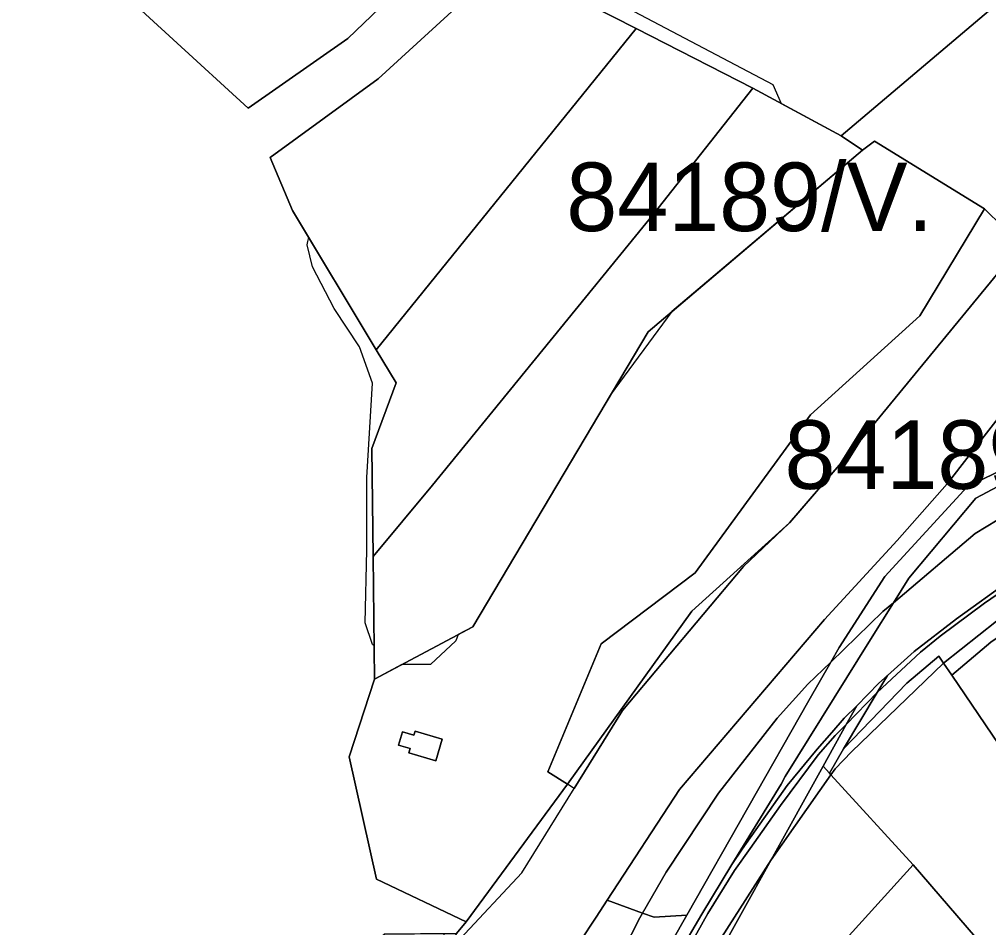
# Model space of a CAD drawing. Extents: x -477304 to -465429, y -1159113 to -1149210.
# Drawn here: x -475692.5 to -475480.3, y -1154385.5 to -1154186.7 of the extents above; entities that cross this region are included whole.
import ezdxf

# ---------------------------------------------------------------- set-up
doc = ezdxf.new("R2010")
doc.units = 0
for name, color, linetype in [('BPEJ_s', 7, 'Continuous'), ('orna_s', 7, 'Continuous'), ('ostatni_s', 7, 'Continuous'), ('PUPFL_s', 7, 'Continuous'), ('trav_porost_s', 7, 'Continuous'), ('voda_s', 7, 'Continuous')]:
    doc.layers.add(name, color=color, linetype=linetype)

msp = doc.modelspace()

# ---------------------------------------------------------------- linework, layer by layer
at = {"layer": 'BPEJ_s'}
for points in [[(-475567.62, -1154179.77), (-475527.61, -1154200.97), (-475525.77, -1154205.09), (-475512.65, -1154212.2), (-475507.98, -1154215.32), (-475549.67, -1154250.64), (-475563.18, -1154268.99), (-475593.29, -1154319.68), (-475596.43, -1154321.35), (-475596.98, -1154322.75), (-475602.54, -1154327.92), (-475608.78, -1154327.92), (-475614.77, -1154331.11), (-475614.86, -1154323.82), (-475615.25, -1154323.55), (-475616.84, -1154318.78), (-475616.44, -1154302.88), (-475616.44, -1154286.97), (-475615.25, -1154266.3), (-475618.03, -1154258.35), (-475623.59, -1154250), (-475628.36, -1154240.86), (-475629.55, -1154236.08), (-475629.37, -1154235.29), (-475629.18, -1154234.44), (-475632.72, -1154228.55), (-475637.63, -1154216.91), (-475613.99, -1154199.7), (-475585.15, -1154173.3)], [(-475613.99, -1154199.7), (-475585.15, -1154173.3)], [(-475567.62, -1154179.77), (-475527.61, -1154200.97), (-475525.77, -1154205.09), (-475512.65, -1154212.2), (-475507.98, -1154215.32), (-475549.67, -1154250.64), (-475563.18, -1154268.99), (-475593.29, -1154319.68), (-475596.43, -1154321.35), (-475596.98, -1154322.75), (-475602.54, -1154327.92), (-475608.78, -1154327.92), (-475614.77, -1154331.11), (-475614.86, -1154323.82), (-475615.25, -1154323.55), (-475616.84, -1154318.78), (-475616.44, -1154302.88), (-475616.44, -1154286.97), (-475615.25, -1154266.3), (-475618.03, -1154258.35), (-475623.59, -1154250), (-475628.36, -1154240.86), (-475629.55, -1154236.08), (-475629.37, -1154235.29), (-475629.18, -1154234.44), (-475632.72, -1154228.55), (-475637.63, -1154216.91), (-475613.99, -1154199.7)], [(-475731, -1154455.5), (-475685.5, -1154443.5), (-475658.17, -1154422.75), (-475639.93, -1154406.49), (-475634.73, -1154404.95), (-475631.5, -1154402.5), (-475628.5, -1154401.5), (-475623.92, -1154398.28), (-475621.39, -1154394.73), (-475612.62, -1154386.98), (-475599.44, -1154386.85), (-475596.82, -1154386.82), (-475597.49, -1154388.37), (-475596, -1154388), (-475582.5, -1154373.5), (-475571.09, -1154355.09), (-475572.52, -1154354.12), (-475576.83, -1154351.41), (-475565.18, -1154323.39), (-475544.55, -1154307.85), (-475519.37, -1154273.24), (-475495.41, -1154251.56), (-475481.23, -1154228.2), (-475473.22, -1154236.05)], [(-475639, -1154586), (-475632, -1154559), (-475633.5, -1154543.56), (-475637, -1154507.5), (-475628.67, -1154485.64), (-475625, -1154476), (-475604.41, -1154404.33), (-475600, -1154389), (-475599.44, -1154386.85), (-475596.82, -1154386.82), (-475597.49, -1154388.37), (-475596, -1154388), (-475582.5, -1154373.5), (-475571.09, -1154355.09), (-475560.5, -1154338), (-475534, -1154306.5), (-475524, -1154296.97), (-475523.89, -1154296.86), (-475508.55, -1154279.03), (-475473.22, -1154236.05)]]:
    msp.add_lwpolyline(points, dxfattribs=at)
msp.add_lwpolyline([(-475473.22, -1154236.05), (-475508.55, -1154279.03), (-475523.89, -1154296.86), (-475524, -1154296.97), (-475534, -1154306.5), (-475560.5, -1154338), (-475571.09, -1154355.09), (-475572.52, -1154354.12), (-475576.83, -1154351.41), (-475565.18, -1154323.39), (-475544.55, -1154307.85), (-475519.37, -1154273.24), (-475495.41, -1154251.56), (-475481.23, -1154228.2)], close=True, dxfattribs=at)
at = {"layer": 'orna_s'}
for points in [[(-475481.26, -1154314.53), (-475490.92, -1154321.74), (-475495.28, -1154325.21), (-475504.75, -1154334.08), (-475502.52, -1154330.36), (-475496.65, -1154325.11), (-475487.4, -1154317.93), (-475475.62, -1154309.48), (-475465.15, -1154302.44), (-475455.29, -1154297.28), (-475447.05, -1154293.35), (-475435.79, -1154288.45), (-475427, -1154285.31), (-475409.33, -1154280.37), (-475398.38, -1154278.13), (-475391.57, -1154277.2), (-475391.61, -1154277.99), (-475404.7, -1154280.5), (-475422.23, -1154285.02), (-475437.56, -1154290.12), (-475454.36, -1154297.46), (-475469.21, -1154306.24)], [(-475475.44, -1154320.07), (-475479.85, -1154323.07), (-475488.4, -1154330.28), (-475490.2, -1154327.62), (-475478.6, -1154318.44), (-475452.58, -1154302.04), (-475435.8, -1154294.77), (-475420.54, -1154289.58), (-475403.9, -1154285.81), (-475391.89, -1154283.24), (-475392.05, -1154286.27), (-475410.21, -1154289.79), (-475428.95, -1154295.45), (-475447.26, -1154303.12), (-475463.43, -1154311.9), (-475472.14, -1154317.82)], [(-475434.02, -1154410.43), (-475488.4, -1154330.28), (-475479.85, -1154323.07), (-475475.44, -1154320.07), (-475427.04, -1154391.42), (-475429.04, -1154396.87)], [(-475490.2, -1154327.62), (-475488.4, -1154330.28), (-475434.02, -1154410.43), (-475457.14, -1154424.42), (-475483.2, -1154387.59), (-475496.89, -1154371.78), (-475514.86, -1154352.08), (-475513.91, -1154350.74), (-475510.38, -1154347.08)]]:
    msp.add_lwpolyline(points, close=True, dxfattribs=at)
at = {"layer": 'ostatni_s'}
for points in [[(-475429, -1154162.83), (-475467.72, -1154186.86), (-475478.48, -1154183.29), (-475512.65, -1154212.2), (-475531.93, -1154201.75), (-475557.51, -1154188.7), (-475583.1, -1154175.64)], [(-475471.25, -1154291.93), (-475483.28, -1154299.25), (-475501.18, -1154314.4), (-475497.82, -1154309.02), (-475483.18, -1154291.52), (-475457.82, -1154278.11)], [(-475475.62, -1154309.48), (-475487.4, -1154317.93), (-475496.65, -1154325.11), (-475502.52, -1154330.36), (-475504.39, -1154332.04), (-475509.23, -1154336.94), (-475511.94, -1154339.68), (-475514.7, -1154342.82), (-475517.85, -1154346.45), (-475524.44, -1154354.43), (-475534.28, -1154368.33), (-475536.55, -1154371.7), (-475525.78, -1154354.09), (-475524.91, -1154352.42), (-475506.21, -1154322.47), (-475501.18, -1154314.4), (-475483.28, -1154299.25), (-475471.25, -1154291.93)], [(-475547.98, -1154390.91), (-475543.16, -1154382.57), (-475536.55, -1154371.7), (-475534.28, -1154368.33), (-475524.44, -1154354.43), (-475517.85, -1154346.45), (-475514.7, -1154342.82), (-475511.94, -1154339.68), (-475509.23, -1154336.94), (-475511.53, -1154341.08), (-475513.94, -1154343.5), (-475517.64, -1154347.73), (-475525.93, -1154358.83), (-475532.55, -1154368.21), (-475535.95, -1154373.01), (-475541.83, -1154382.44), (-475549.8, -1154396.65)], [(-475549.8, -1154396.65), (-475541.83, -1154382.44), (-475535.95, -1154373.01), (-475532.55, -1154368.21), (-475525.93, -1154358.83), (-475517.64, -1154347.73), (-475513.94, -1154343.5), (-475511.53, -1154341.08), (-475516.6, -1154350.21), (-475527.96, -1154370.68), (-475538.83, -1154387.7)]]:
    msp.add_lwpolyline(points, dxfattribs=at)
for points in [[(-475468.98, -1154276.86), (-475449, -1154270.5), (-475447.33, -1154269.96), (-475451.89, -1154256.11), (-475447.22, -1154254.31), (-475447, -1154254.98), (-475448.33, -1154255.41), (-475447.49, -1154258.01), (-475446.15, -1154257.58), (-475443.98, -1154264.35), (-475430.63, -1154260.01), (-475434.1, -1154249.27), (-475402.53, -1154237.13), (-475390.95, -1154258.02), (-475405, -1154260.27), (-475423.09, -1154264.6), (-475458.7, -1154276.34), (-475484.98, -1154288.97), (-475489.4, -1154288.4), (-475469.65, -1154262.94), (-475463.12, -1154260.43), (-475470.7, -1154270.78)], [(-475514.92, -1154327.4), (-475513.1, -1154324.2), (-475503.04, -1154308.64), (-475484.98, -1154288.97), (-475458.7, -1154276.34), (-475423.09, -1154264.6), (-475405, -1154260.27), (-475422.7, -1154265.96), (-475457.82, -1154278.11), (-475483.18, -1154291.52), (-475497.82, -1154309.02), (-475501.18, -1154314.4), (-475503.47, -1154316.34)], [(-475481.26, -1154314.53), (-475469.21, -1154306.24), (-475454.36, -1154297.46), (-475437.56, -1154290.12), (-475422.23, -1154285.02), (-475404.7, -1154280.5), (-475391.61, -1154277.99), (-475391.78, -1154281.13), (-475391.89, -1154283.24), (-475403.9, -1154285.81), (-475420.54, -1154289.58), (-475435.8, -1154294.77), (-475452.58, -1154302.04), (-475478.6, -1154318.44), (-475490.2, -1154327.62), (-475491.22, -1154326.12), (-475498.22, -1154332.03), (-475512.15, -1154346.39), (-475504.75, -1154334.08), (-475495.28, -1154325.21), (-475490.92, -1154321.74)], [(-475560.13, -1154406.85), (-475546.44, -1154382.79), (-475519.7, -1154335.8), (-475514.92, -1154327.4), (-475503.47, -1154316.34), (-475501.18, -1154314.4), (-475506.21, -1154322.47), (-475524.91, -1154352.42), (-475525.78, -1154354.09), (-475536.55, -1154371.7), (-475543.16, -1154382.57), (-475547.98, -1154390.91), (-475568.51, -1154422.5)], [(-475546.44, -1154382.79), (-475553.59, -1154383.27), (-475556.1, -1154382.36), (-475550.91, -1154373.36), (-475539.48, -1154356.13), (-475526.66, -1154339.71), (-475519.94, -1154332.25), (-475514.92, -1154327.4), (-475519.7, -1154335.8)], [(-475512.15, -1154346.39), (-475498.22, -1154332.03), (-475491.22, -1154326.12), (-475490.2, -1154327.62), (-475510.38, -1154347.08), (-475513.91, -1154350.74), (-475514.86, -1154352.08), (-475515.21, -1154351.7)], [(-475509.23, -1154336.94), (-475504.39, -1154332.04), (-475502.52, -1154330.36), (-475504.75, -1154334.08), (-475511.53, -1154341.08)], [(-475511.53, -1154341.08), (-475504.75, -1154334.08), (-475512.15, -1154346.39), (-475515.21, -1154351.7), (-475516.6, -1154350.21)], [(-475599.97, -1154344.29), (-475601.38, -1154349.02), (-475607.28, -1154347.26), (-475607, -1154346.32), (-475609.51, -1154345.57), (-475608.65, -1154342.67), (-475606.14, -1154343.42), (-475605.87, -1154342.53)], [(-475527.96, -1154370.68), (-475516.6, -1154350.21), (-475515.21, -1154351.7), (-475514.86, -1154352.08)], [(-475538.83, -1154387.7), (-475527.96, -1154370.68), (-475541.24, -1154394.59)], [(-475546.44, -1154382.79), (-475560.13, -1154406.85), (-475568.51, -1154422.5), (-475579.97, -1154449.97), (-475583.73, -1154445.03), (-475574.25, -1154419.9), (-475565.96, -1154401.53), (-475556.68, -1154383.37), (-475556.1, -1154382.36), (-475553.59, -1154383.27)]]:
    msp.add_lwpolyline(points, close=True, dxfattribs=at)
at = {"layer": 'PUPFL_s'}
for points in [[(-475352.75, -1153984.87), (-475338.69, -1154011.34), (-475352.09, -1154014.95), (-475381.35, -1154022.83), (-475443.17, -1154025.66), (-475499.82, -1154029.51), (-475556.44, -1154021.02), (-475635.42, -1154012.08), (-475649.02, -1154046.75), (-475671.45, -1154068.19), (-475660.13, -1154079.7), (-475654.25, -1154085.13), (-475651.23, -1154087.99), (-475623.48, -1154114.25), (-475601.71, -1154149.02), (-475588.2, -1154168.75), (-475594.61, -1154165.94), (-475620.6, -1154190.85), (-475642.43, -1154206.13), (-475806.71, -1154055.75), (-475825.65, -1154044.41), (-475814.03, -1153985.87)], [(-475814.03, -1153985.87), (-475825.65, -1154044.41), (-475806.71, -1154055.75), (-475642.43, -1154206.13), (-475620.6, -1154190.85), (-475594.61, -1154165.94), (-475588.2, -1154168.75), (-475585.15, -1154173.3), (-475613.99, -1154199.7), (-475637.63, -1154216.91), (-475632.72, -1154228.55), (-475614.41, -1154259.01), (-475610.06, -1154266.26), (-475615.38, -1154280.61)], [(-475615.38, -1154280.61), (-475615.09, -1154304.29), (-475614.77, -1154331.11), (-475620.34, -1154348.16)], [(-475620.34, -1154348.16), (-475614.32, -1154374.89), (-475594.73, -1154384.24), (-475596.82, -1154386.82), (-475612.62, -1154386.98), (-475621.39, -1154394.73), (-475627.06, -1154402.68), (-475639.93, -1154406.49), (-475666.83, -1154430.47), (-475692.56, -1154448.71)]]:
    msp.add_lwpolyline(points, dxfattribs=at)
for points in [[(-475473.22, -1154236.05), (-475481.23, -1154228.2), (-475505.35, -1154213.34), (-475507.98, -1154215.32), (-475512.65, -1154212.2), (-475478.48, -1154183.29), (-475467.72, -1154186.86), (-475429, -1154162.83), (-475426.04, -1154160.45), (-475422.46, -1154165.86), (-475426.6, -1154166.59), (-475414.25, -1154197.63), (-475438.58, -1154204.34), (-475454.72, -1154212.8), (-475465.22, -1154223.55)], [(-475565.18, -1154323.39), (-475576.83, -1154351.41), (-475572.52, -1154354.12), (-475594.73, -1154384.24), (-475614.32, -1154374.89), (-475620.34, -1154348.16), (-475614.77, -1154331.11), (-475593.29, -1154319.68), (-475554.91, -1154255.08), (-475507.98, -1154215.32), (-475505.35, -1154213.34), (-475481.23, -1154228.2), (-475495.41, -1154251.56), (-475519.37, -1154273.24), (-475544.55, -1154307.85)], [(-475607.28, -1154347.26), (-475601.38, -1154349.02), (-475599.97, -1154344.29), (-475605.87, -1154342.53), (-475606.14, -1154343.42), (-475608.65, -1154342.67), (-475609.51, -1154345.57), (-475607, -1154346.32)]]:
    msp.add_lwpolyline(points, close=True, dxfattribs=at)
at = {"layer": 'trav_porost_s'}
for points in [[(-475637.63, -1154216.91), (-475613.99, -1154199.7), (-475585.15, -1154173.3), (-475583.1, -1154175.64), (-475557.51, -1154188.7), (-475614.41, -1154259.01), (-475632.72, -1154228.55)], [(-475531.93, -1154201.75), (-475553.75, -1154229.42), (-475602.05, -1154288.69), (-475615.09, -1154304.29), (-475615.38, -1154280.61), (-475610.06, -1154266.26), (-475614.41, -1154259.01), (-475557.51, -1154188.7)], [(-475615.09, -1154304.29), (-475602.05, -1154288.69), (-475553.75, -1154229.42), (-475531.93, -1154201.75), (-475512.65, -1154212.2), (-475507.98, -1154215.32), (-475554.91, -1154255.08), (-475593.29, -1154319.68), (-475614.77, -1154331.11)], [(-475473.22, -1154236.05), (-475508.55, -1154279.03), (-475523.9, -1154296.88), (-475545.3, -1154316.22), (-475572.52, -1154354.12), (-475576.83, -1154351.41), (-475565.18, -1154323.39), (-475544.55, -1154307.85), (-475519.37, -1154273.24), (-475495.41, -1154251.56), (-475481.23, -1154228.2)], [(-475550.91, -1154373.36), (-475556.1, -1154382.36), (-475563.87, -1154379.55), (-475548.04, -1154355.26), (-475516.26, -1154318.07), (-475500.36, -1154300.77), (-475489.4, -1154288.4), (-475484.98, -1154288.97), (-475503.04, -1154308.64), (-475513.1, -1154324.2), (-475514.92, -1154327.4), (-475519.94, -1154332.25), (-475526.66, -1154339.71), (-475539.48, -1154356.13)], [(-475541.24, -1154394.59), (-475527.96, -1154370.68), (-475514.86, -1154352.08), (-475496.89, -1154371.78), (-475528.32, -1154406.52)], [(-475509.34, -1154455.82), (-475528.72, -1154440.81), (-475536.42, -1154435.75), (-475541.79, -1154431.04), (-475534.27, -1154422.32), (-475537.4, -1154418.92), (-475538.34, -1154419.92), (-475539.47, -1154418.94), (-475538.56, -1154417.92), (-475537.44, -1154416.66), (-475534.42, -1154413.26), (-475528.32, -1154406.52), (-475496.89, -1154371.78), (-475483.2, -1154387.59), (-475457.14, -1154424.42), (-475492.65, -1154458.11)], [(-475565.96, -1154401.53), (-475574.25, -1154419.9), (-475583.73, -1154445.03), (-475591.13, -1154435.31), (-475587.85, -1154420.49), (-475580.57, -1154404.81), (-475566.27, -1154383.22), (-475563.87, -1154379.55), (-475556.1, -1154382.36), (-475556.68, -1154383.37)]]:
    msp.add_lwpolyline(points, close=True, dxfattribs=at)
at = {"layer": 'voda_s'}
for points in [[(-475638.79, -1154574.99), (-475635.34, -1154556), (-475629.49, -1154516.48), (-475628.16, -1154466.27), (-475624.86, -1154446.16), (-475614, -1154423.69), (-475611.22, -1154417.76), (-475607.97, -1154412.56), (-475596.82, -1154386.82), (-475594.73, -1154384.24), (-475572.52, -1154354.12), (-475545.3, -1154316.22), (-475523.9, -1154296.88), (-475508.55, -1154279.03), (-475473.22, -1154236.05)], [(-475469.65, -1154262.94), (-475489.4, -1154288.4), (-475500.36, -1154300.77), (-475516.26, -1154318.07), (-475548.04, -1154355.26), (-475563.87, -1154379.55), (-475566.27, -1154383.22), (-475580.57, -1154404.81), (-475587.85, -1154420.49), (-475591.13, -1154435.31), (-475592.8, -1154442.83), (-475595.24, -1154451.62), (-475605.62, -1154483.63), (-475611.68, -1154539.06), (-475612.04, -1154541.98), (-475610.84, -1154542.48), (-475616.12, -1154563.49), (-475618.75, -1154572.09)]]:
    msp.add_lwpolyline(points, dxfattribs=at)

# ---------------------------------------------------------------- texts
at = {"layer": 'BPEJ_s'}
for p in [(-475572.8, -1154233.04), (-475525.03, -1154289.48)]:
    msp.add_text('84189/V.', height=15, dxfattribs=at).set_placement(p)

doc.saveas('drawing.dxf')
